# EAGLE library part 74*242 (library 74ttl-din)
Quadruple BUS TRANSCEIVER
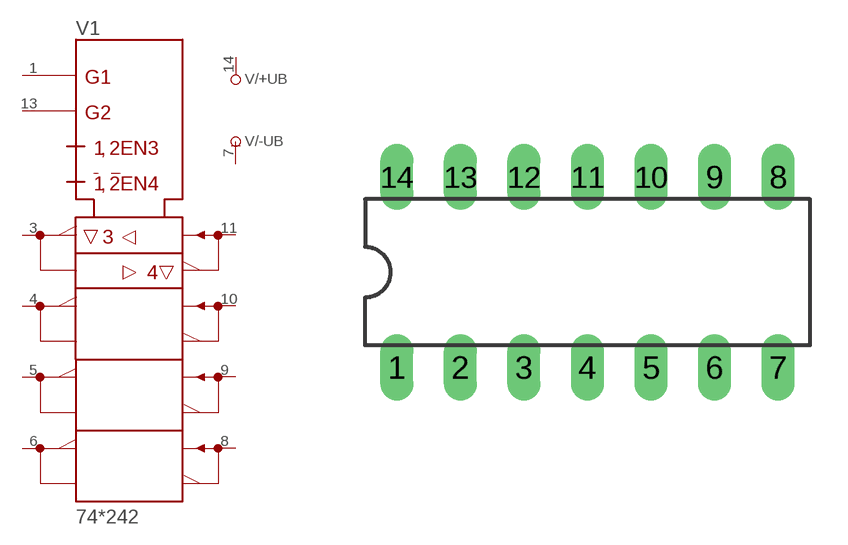
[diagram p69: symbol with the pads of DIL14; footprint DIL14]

Designator prefix V; gates /+UB=+UB /-UB=-UB 1=242

## 74242N  [DIL14]
1  1:G1  in
3  1:A1
4  1:A2
5  1:A3
6  1:A4
7  /-UB:-UB  pwr
8  1:B4
9  1:B3
10  1:B2
11  1:B1
13  1:G2  in
14  /+UB:+UB  pwr

## Footprint DIL14 (pad centres in mm)
Dual In Line Package
drill 0.813 long: 1 -7.62,-3.81; 2 -5.08,-3.81; 3 -2.54,-3.81; 4 0,-3.81; 5 2.54,-3.81; 6 5.08,-3.81; 7 7.62,-3.81; 8 7.62,3.81; 9 5.08,3.81; 10 2.54,3.81; 11 0,3.81; 12 -2.54,3.81; 13 -5.08,3.81; 14 -7.62,3.81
